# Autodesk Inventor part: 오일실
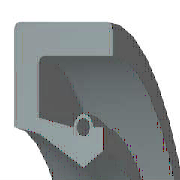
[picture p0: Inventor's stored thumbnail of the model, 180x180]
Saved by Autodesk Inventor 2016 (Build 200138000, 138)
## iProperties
IsCustomPart: 1
Created: 2015-10
Part Number: 오일실
Material: 고무
Description: 오일-실
Document SubType Name: Modeling
Standard: KS B 2804
Designer: mdu
Standards Organization: KS
Language: ko-KR
Size Designation: S - 25 38 8
Categories: <MemberInstance><Categories><Category DisplayName="샤프트 부품" InternalName="7f7aeb1f-a693-4053-b835-cee3144e0d98" Mnemonic="SHFT"><Category DisplayName="실링" Intern
Density: 0.93 g/cm^3
Appearance: 고무 - 검은색 - 버전 1.1
Mass: 2.23721 g
Surface Area: 37.0166 cm^2
Volume: 2.4056 cm^3
Author: mdu
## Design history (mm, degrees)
revolve "본체" stored, may be unused: angle "d17" = 90 deg
revolve "스프링1" stored, may be unused: angle "d18" = 90 deg
body "Solid1"
sketch "스케치1"
  geometry: L1 (0, 19)-(8, 19); L2 (8, 19)-(8, 17.75); L3 (8, 17.75)-(1.75, 17.75); L4 (0, 19)-(0, 14.6); L5 (0, 14.6)-(1.75, 14.25); L6 (1.75, 14.25)-(4.9, 12.5); L7 (4.9, 12.5)-(0, 12.5); L8 (6.3, 13.375)-(6.3, 14.6); L9 (0, 0)-(9.586, 0) reference; L10 (4.9, 12.5)-(6.3, 13.375); L11 (0, 18)-(0, -3) reference; L12 (-1.917, 0)-(11.503, 0) reference; L13 (4.2, 14.6)-(1.75, 15.09); L14 (1.75, 15.09)-(1.75, 17.75); L15 (6.3, 14.6)-(5.6, 14.6); C1 r 0.455 at (4.9, 14.6); A1 r 0.7 centre (4.9, 14.6) between (5.6, 14.6) and (4.2, 14.6)
  constraints: 26 end point, 5 horizontal alignment, 4 perpendicular, 2 centre point, 2 collinear, 2 horizontal, 2 parallel, 2 point on circle, 2 point on line, 2 vertical alignment, 1 coincident
  dimensions: "d0" = 38 diameter of L1 L9 (= SD2); "d1" = 26.75 diameter of L8.start L9 (= ABDM); "d2" = 1.25 distance of L1.end L2.end (computed from SD); "d3" = 0.91 diameter of C1 (= SPDI); "d4" = 1.4 diameter of A1 (= SPDA); "d5" = 25 diameter of L6.end L9 (= NND); "d6" = 28.5 diameter of L5.end L9 (= TKDM); "d7" = 29.2 diameter of L4.end L9 (= HLDM); "d8" = 4.9 distance from line of C1.centre L4 (= SPDST); "d9" = 6.3 distance between parallel lines of L8 L4 (= SDI); "d10" = 8 distance between parallel lines of L2 L4 (= SWDT); "d12" = 1.75 distance between parallel lines of L14 L4 (= SD)
fillet "모깎기1" dims "d11" = 0.3 (= RR)
other parameters: "SD2" = 38 [user parameter; used in 1 equation term], "SWDT" = 8 [user parameter; used in 1 equation term], "RR" = 0.3 [user parameter; used in 1 equation term], "SD" = 1.75 [user parameter; used in 2 equation terms], "NND" = 25 [user parameter; used in 1 equation term], "SPDA" = 1.4 [user parameter; used in 1 equation term], "SPDI" = 0.91 [user parameter; used in 1 equation term], "TKDM" = 28.5 [user parameter; used in 1 equation term], "HLDM" = 29.2 [user parameter; used in 1 equation term], "ABDM" = 26.75 [user parameter; used in 1 equation term], "SDI" = 6.3 [user parameter; used in 1 equation term], "SPDST" = 4.9 [user parameter; used in 1 equation term], "d13" = 0, "d14" = 0, "d15" = 0, "LAB" = 0.35 [user parameter]
